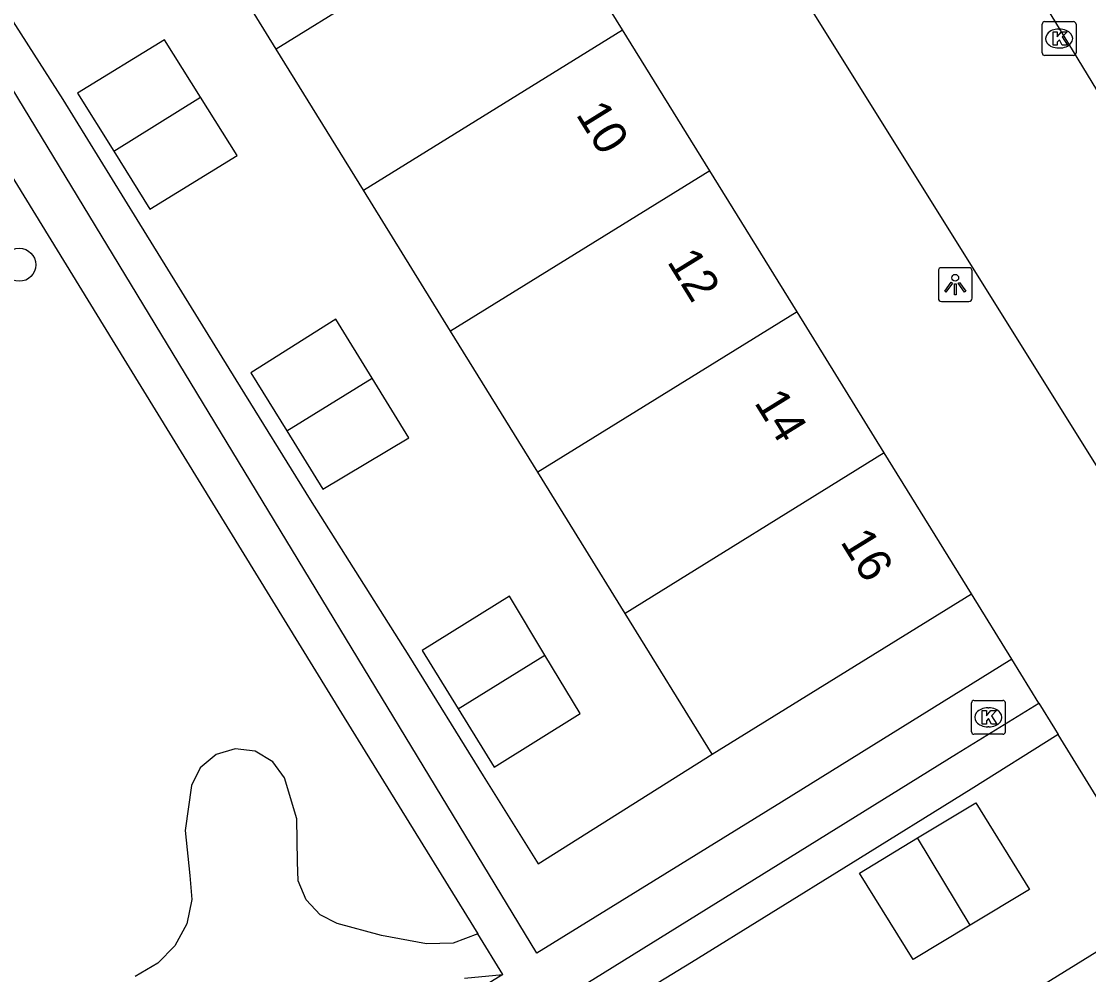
# Model space of a CAD drawing. Extents: x 159888 to 160757, y 384031 to 384746.
# Drawn here: x 160186.63 to 160218.18, y 384559.5 to 384587.67 of the extents above; entities that cross this region are included whole.
import ezdxf

# ---------------------------------------------------------------- set-up
doc = ezdxf.new("R2010")
doc.units = 0
for name, color, linetype in [('IMGEO_Boom', 7, 'Continuous'), ('IMGEO_Groenvoorziening', 7, 'Continuous'), ('IMGEO_Kolk', 7, 'Continuous'), ('IMGEO_Lichtpunt', 7, 'Continuous'), ('IMGEO_Pand', 7, 'Continuous'), ('IMGEO_Pand_nummerreeks', 7, 'Continuous'), ('IMGEO_Rijbaan_lokaal_open', 7, 'Continuous'), ('IMGEO_Voetpad_open', 7, 'Continuous')]:
    doc.layers.add(name, color=color, linetype=linetype)

msp = doc.modelspace()

# ---------------------------------------------------------------- linework, layer by layer
at = {"layer": 'IMGEO_Boom'}
msp.add_circle((160186.573, 384580.476), 0.489, dxfattribs=at)
at = {"layer": 'IMGEO_Groenvoorziening'}
for points in [[(160178.522, 384600.227), (160179.656, 384598.411), (160182.706, 384593.538), (160184.899, 384589.992), (160187.856, 384585.356), (160190.049, 384581.81), (160192.976, 384577.075), (160195.169, 384573.529), (160198.086, 384568.923), (160200.279, 384565.377), (160201.907, 384562.777), (160207.047, 384566.013)], [(160217.276, 384566.598), (160214.703, 384564.976), (160211.144, 384562.778), (160206.438, 384559.861), (160202.905, 384557.7), (160198.249, 384554.781), (160194.673, 384552.612), (160189.978, 384549.717), (160186.466, 384547.528), (160181.751, 384544.625), (160178.213, 384542.424), (160173.521, 384539.537), (160169.984, 384537.335), (160167.391, 384535.745), (160167.622, 384535.376), (160170.612, 384530.605)], [(160200.122, 384560.709), (160199.392, 384560.432), (160198.612, 384560.41), (160197.276, 384560.656), (160195.965, 384561.012), (160195.461, 384561.272), (160195.051, 384561.713), (160194.82, 384562.27), (160194.794, 384562.837), (160194.775, 384564.1), (160194.416, 384565.311), (160194.071, 384565.788), (160193.542, 384566.099), (160192.958, 384566.17), (160192.393, 384566.005), (160191.923, 384565.611), (160191.66, 384565.085), (160191.474, 384563.759), (160191.612, 384562.428), (160191.671, 384561.721), (160191.522, 384560.997), (160191.171, 384560.347), (160190.671, 384559.844), (160190.001, 384559.449)], [(160199.731, 384559.395), (160200.868, 384559.503)]]:
    msp.add_lwpolyline(points, dxfattribs=at)
at = {"layer": 'IMGEO_Kolk'}
for p, q in [((160216.804, 384586.735), (160216.804, 384587.587)), ((160216.879, 384587.661), (160217.731, 384587.661)), ((160217.292, 384587.441), (160217.317, 384587.441)), ((160217.805, 384587.587), (160217.805, 384586.735)), ((160217.315, 384586.881), (160217.29, 384586.881)), ((160217.731, 384586.661), (160216.879, 384586.661)), ((160214.714, 384566.677), (160214.714, 384567.529)), ((160214.789, 384567.603), (160215.641, 384567.603)), ((160215.715, 384567.529), (160215.715, 384566.677)), ((160215.202, 384567.383), (160215.227, 384567.383)), ((160215.641, 384566.603), (160214.789, 384566.603)), ((160215.225, 384566.823), (160215.2, 384566.823))]:
    msp.add_line(p, q, dxfattribs=at)
for points in [[(160216.804, 384586.735), (160216.804, 384587.587)], [(160216.879, 384587.661), (160217.731, 384587.661)], [(160217.805, 384587.587), (160217.805, 384586.735)], [(160217.125, 384587.361), (160217.248, 384587.361), (160217.248, 384587.21), (160217.378, 384587.361), (160217.542, 384587.361), (160217.396, 384587.21), (160217.549, 384586.961), (160217.397, 384586.961), (160217.312, 384587.125), (160217.248, 384587.058), (160217.248, 384586.961), (160217.125, 384586.961), (160217.125, 384587.361)], [(160217.731, 384586.661), (160216.879, 384586.661)], [(160214.714, 384566.677), (160214.714, 384567.529)], [(160214.789, 384567.603), (160215.641, 384567.603)], [(160215.715, 384567.529), (160215.715, 384566.677)], [(160215.035, 384567.303), (160215.158, 384567.303), (160215.158, 384567.152), (160215.288, 384567.303), (160215.452, 384567.303), (160215.306, 384567.152), (160215.459, 384566.903), (160215.307, 384566.903), (160215.222, 384567.067), (160215.158, 384567), (160215.158, 384566.903), (160215.035, 384566.903), (160215.035, 384567.303)], [(160215.641, 384566.603), (160214.789, 384566.603)]]:
    msp.add_lwpolyline(points, dxfattribs=at)
for centre, start, end in [((160216.881, 384587.585), 91.552, 178.448), ((160216.881, 384587.585), 91.552, 178.448), ((160217.729, 384587.585), 1.552, 88.448), ((160217.729, 384587.585), 1.552, 88.448), ((160216.881, 384586.737), 181.552, 268.448), ((160216.881, 384586.737), 181.552, 268.448), ((160217.729, 384586.737), 271.552, 358.448), ((160217.729, 384586.737), 271.552, 358.448), ((160214.791, 384567.527), 91.552, 178.448), ((160214.791, 384567.527), 91.552, 178.448), ((160215.639, 384567.527), 1.552, 88.448), ((160215.639, 384567.527), 1.552, 88.448), ((160214.791, 384566.679), 181.552, 268.448), ((160214.791, 384566.679), 181.552, 268.448), ((160215.639, 384566.679), 271.552, 358.448), ((160215.639, 384566.679), 271.552, 358.448)]:
    msp.add_arc(centre, 0.0765, start, end, dxfattribs=at)
for centre, major_axis, ratio, start_param, end_param in [((160217.291, 384587.161), (-0.387, 0.002), 0.722429, 4.712389, 7.853982), ((160217.316, 384587.161), (-0.39, 0.002), 0.717154, 1.570796, 4.712389), ((160215.201, 384567.103), (-0.387, 0.002), 0.722429, 4.712389, 7.853982), ((160215.226, 384567.103), (-0.39, 0.002), 0.717154, 1.570796, 4.712389)]:
    msp.add_ellipse(centre, major_axis=major_axis, ratio=ratio, start_param=start_param, end_param=end_param, dxfattribs=at)
at = {"layer": 'IMGEO_Lichtpunt'}
for p, q in [((160213.736, 384580.294), (160213.736, 384579.487)), ((160213.736, 384580.294), (160213.736, 384579.487)), ((160214.638, 384580.389), (160213.83, 384580.389)), ((160214.638, 384580.389), (160213.83, 384580.389)), ((160214.732, 384579.487), (160214.732, 384580.294)), ((160214.732, 384579.487), (160214.732, 384580.294)), ((160213.83, 384579.393), (160214.638, 384579.393)), ((160213.83, 384579.393), (160214.638, 384579.393))]:
    msp.add_line(p, q, dxfattribs=at)
for points in [[(160214.11, 384579.958), (160214.149, 384579.93), (160213.961, 384579.668), (160213.923, 384579.695), (160214.11, 384579.958)], [(160214.212, 384579.91), (160214.259, 384579.91), (160214.259, 384579.588), (160214.212, 384579.588), (160214.212, 384579.91)], [(160214.322, 384579.93), (160214.36, 384579.957), (160214.547, 384579.695), (160214.508, 384579.667), (160214.322, 384579.93)]]:
    msp.add_lwpolyline(points, dxfattribs=at)
msp.add_circle((160214.235, 384580.092), 0.0994, dxfattribs=at)
for centre, start, end in [((160213.83, 384580.294), 90, 180), ((160213.83, 384580.294), 90, 180), ((160214.638, 384580.294), 0, 90), ((160214.638, 384580.294), 0, 90), ((160213.83, 384579.487), 180, 270), ((160213.83, 384579.487), 180, 270), ((160214.638, 384579.487), 270, 0), ((160214.638, 384579.487), 270, 360)]:
    msp.add_arc(centre, 0.0946, start, end, dxfattribs=at)
at = {"layer": 'IMGEO_Pand'}
for points in [[(160201.822, 384591.587), (160194.168, 384586.85)], [(160204.401, 384587.419), (160201.822, 384591.587)], [(160194.168, 384586.85), (160191.591, 384591.019)], [(160196.745, 384582.681), (160204.401, 384587.419)], [(160206.98, 384583.252), (160204.401, 384587.419)], [(160191.931, 384585.431), (160190.866, 384587.126), (160188.295, 384585.545), (160189.364, 384583.831)], [(160196.745, 384582.681), (160194.168, 384586.85)], [(160189.364, 384583.831), (160191.931, 384585.431)], [(160189.364, 384583.831), (160190.433, 384582.116), (160193.015, 384583.707), (160191.931, 384585.431)], [(160206.98, 384583.252), (160199.321, 384578.512)], [(160209.559, 384579.085), (160206.98, 384583.252)], [(160199.321, 384578.512), (160196.745, 384582.681)], [(160197.001, 384577.123), (160195.931, 384578.87), (160193.416, 384577.286), (160194.48, 384575.565)], [(160209.559, 384579.085), (160201.898, 384574.344)], [(160212.138, 384574.917), (160209.559, 384579.085)], [(160201.898, 384574.344), (160199.321, 384578.512)], [(160194.48, 384575.565), (160197.001, 384577.123)], [(160194.48, 384575.565), (160195.544, 384573.843), (160198.082, 384575.359), (160197.001, 384577.123)], [(160212.138, 384574.917), (160204.475, 384570.175)], [(160214.717, 384570.75), (160212.138, 384574.917)], [(160204.475, 384570.175), (160201.898, 384574.344)], [(160202.109, 384568.939), (160201.062, 384570.679), (160198.482, 384569.074), (160199.545, 384567.354)], [(160207.047, 384566.013), (160214.717, 384570.75)], [(160207.047, 384566.013), (160204.475, 384570.175)], [(160199.545, 384567.354), (160202.109, 384568.939)], [(160199.545, 384567.354), (160200.609, 384565.634), (160203.149, 384567.212), (160202.109, 384568.939)], [(160213.123, 384563.539), (160214.841, 384564.577), (160216.425, 384562.02), (160214.678, 384560.966)], [(160214.678, 384560.966), (160212.996, 384559.95), (160211.405, 384562.5), (160213.123, 384563.539)], [(160214.678, 384560.966), (160213.123, 384563.539)], [(160220.459, 384561.433), (160216.305, 384558.864)]]:
    msp.add_lwpolyline(points, dxfattribs=at)
at = {"layer": 'IMGEO_Rijbaan_lokaal_open'}
msp.add_lwpolyline([(160221.001, 384574.011), (160220.988, 384574.411), (160220.948, 384581.486), (160203.247, 384610.565), (160202.928, 384611.063), (160201.451, 384612.336)], dxfattribs=at)
at = {"layer": 'IMGEO_Voetpad_open'}
for points in [[(160201.584, 384611.287), (160197.09, 384608.642), (160218.869, 384573.782), (160219.37, 384572.961), (160221.001, 384574.011)], [(160215.907, 384568.818), (160209.103, 384564.601), (160201.865, 384560.132), (160178.233, 384599.071), (160177.796, 384599.792)], [(160200.868, 384559.503), (160163.406, 384536.375), (160152.94, 384553.3), (160148.281, 384560.789), (160181.266, 384581.183), (160180.644, 384582.188), (160185.149, 384585.056), (160186.066, 384583.561), (160189.322, 384578.257), (160196.17, 384567.098), (160200.122, 384560.709)], [(160215.907, 384568.818), (160214.717, 384570.75)], [(160216.709, 384567.521), (160215.907, 384568.818)], [(160172.677, 384521.294), (160170.426, 384524.933), (160164.199, 384535.04), (160201.679, 384558.218), (160214.269, 384566.02), (160216.709, 384567.521)], [(160216.709, 384567.521), (160217.169, 384566.771), (160217.276, 384566.598)], [(160220.459, 384561.433), (160217.276, 384566.598)], [(160200.868, 384559.503), (160200.122, 384560.709)]]:
    msp.add_lwpolyline(points, dxfattribs=at)

# ---------------------------------------------------------------- texts
at = {"layer": 'IMGEO_Pand_nummerreeks'}
for s, p in [('10', (160203.006, 384584.921)), ('12', (160205.701, 384580.567)), ('14', (160208.276, 384576.407)), ('16', (160210.821, 384572.293))]:
    msp.add_text(s, height=1, rotation=301.7531, dxfattribs=at).set_placement(p)

doc.saveas('drawing.dxf')
